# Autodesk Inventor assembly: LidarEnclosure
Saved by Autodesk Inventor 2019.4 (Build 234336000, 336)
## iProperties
Created: 2020-05
Part Number: LidarEnclosure
Document SubType Name: Assembly
Designer: Administrator
Title: LidarEnclosure v15
Author: Administrator
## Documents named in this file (5)
- c:\worker\convert-fusion-r04\tmp\job-1\3\output\files\88492291-068e-4573-82a5-cdd8cfb136cd\d995f2fa-2eb7-42cc-867a-2590dfc18700.iam
- c:\worker\convert-fusion-r04\tmp\job-1\3\output\files\88492291-068e-4573-82a5-cdd8cfb136cd\Lidar Enclosure Base.ipt
- c:\worker\convert-fusion-r04\tmp\job-1\3\output\files\88492291-068e-4573-82a5-cdd8cfb136cd\Lidar Enclosure Lid.ipt
- c:\worker\convert-fusion-r04\tmp\job-1\3\output\files\88492291-068e-4573-82a5-cdd8cfb136cd\rplidar-a2m4-r1 v2.iam
- c:\worker\convert-fusion-r04\tmp\job-1\3\output\files\88492291-068e-4573-82a5-cdd8cfb136cd\AcrylicTube.ipt
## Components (4 placed, 4 different names)
1. Lidar Enclosure Base:1
2. Lidar Enclosure Lid:1
3. rplidar-a2m4-r1 v2:1 [sub-assembly]
4. AcrylicTube:1
